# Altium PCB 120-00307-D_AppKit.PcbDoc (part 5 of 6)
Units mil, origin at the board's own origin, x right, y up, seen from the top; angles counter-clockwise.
Board outline 5150 x 3100 mil, 6 copper layers (L1, L2 (GND), L3-SIG, L4-SIG, L5 (PWR), L6), stack 61.956 mil thick; 413 components, 344 nets, 1685 pads, 1021 vias.
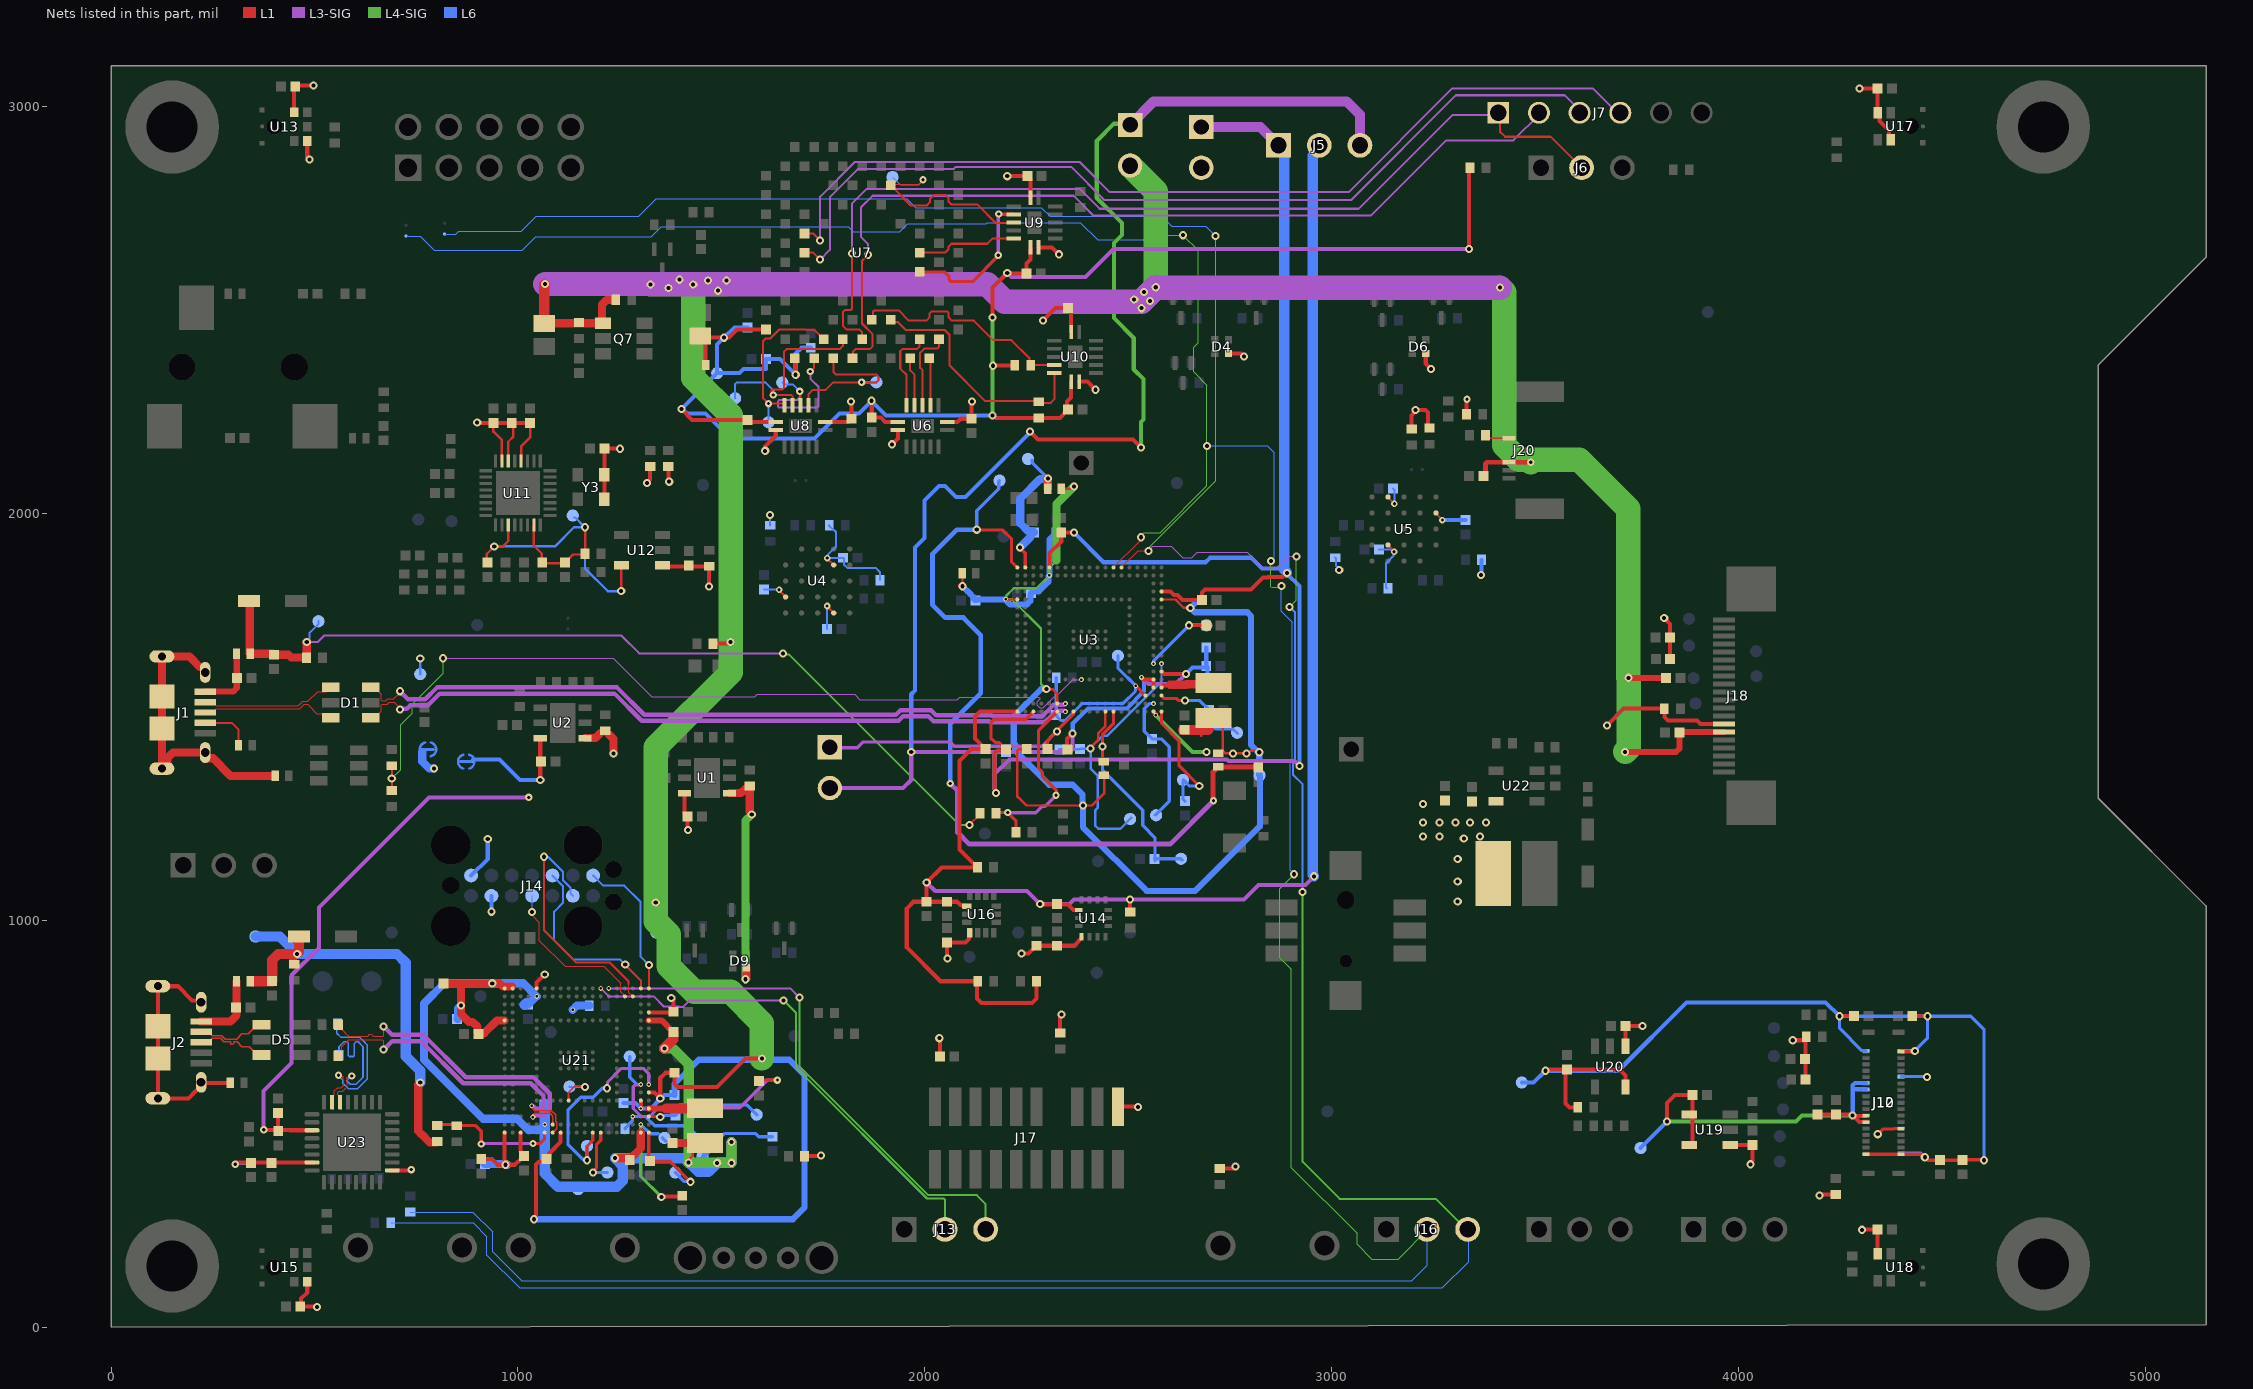
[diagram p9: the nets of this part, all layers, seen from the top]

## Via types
v1: diameter 20, hole 10, L1 to L6, tented both sides, 437 vias
v2: diameter 20, hole 10, L1 to L6, 330 vias
v3: diameter 12, hole 6, L1 to L6, tented both sides, 120 vias
v4: diameter 18, hole 8, L1 to L6, 93 vias
v5: diameter 16, hole 8, L1 to L6, tented both sides, 41 vias

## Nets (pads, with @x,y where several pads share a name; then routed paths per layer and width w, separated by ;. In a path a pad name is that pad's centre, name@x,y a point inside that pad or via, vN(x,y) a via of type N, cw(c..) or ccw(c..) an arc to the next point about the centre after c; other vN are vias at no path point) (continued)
SEUART_RX: J16.3 R105.1 S8.2 U3.A14 | length 8155.6
  L1 w3: U3.A14@2483.74,1867.16 2524.57,1908 v2(2550,1908)
  L3-SIG w3: v2(2550,1908) 2561,1919 2606,1919 2634,1891 2656,1891 2670,1905 2793,1905 2832,1866 2865,1866 2894,1895 v2@2914,1895 ; v2@2913.5,1894.5 v2(2914,1894)
  L4-SIG w3: v2(2550,1908) 2553.25,1911.25 2553.25,1918.25 2715,2080 v2(2715,2682) ; v2(2897,1770) 2914,1787 v2(2914,1894)
  L4-SIG w5: v2(2929,1069) 2929,406 3020,315 3256,315 J16.3@3337,234
  L6 w3: R105.1@687.68,256 890,256 924,222 924,176 1004,96 3272,96 3337,161 3337,243 J16.3@3339,245 ; S8.2@820,2686.7 847.7,2686.7 855,2694 1008,2694 1045,2731 1297,2731 1340,2774 1956,2774 1978,2752 2287,2752 2309,2730 2584,2730 2608,2706 2691,2706 v2(2715,2682)
  L6 w5: v2(2897,1770) 2910.5,1756.5 2910.5,1390.42 2905.5,1385.42 2905.5,1357.5 2929,1334 v2(2929,1069)
SEUART_RX_J: J13.3 U21.A14 | length 1307.3
  L3-SIG w5: v3(1223.43,832.48) 1669.52,832.48 v2(1692,810)
  L4-SIG w5: v2(1692,810) 1692,641 2009,324 2128,324 2150,302 J13.3@2150,240
SEUART_TX: J16.2 R106.1 S9.2 U3.A13 | length 8159.7
  L1 w3: U3.A13@2464.05,1867.16 2528.75,1931.86 2528.75,1938.25 v2(2532,1941.5)
  L4-SIG w3: v2(2532,1941.5) 2532,1946.1 2536.76,1950.86 2536.76,1951.24 2538.52,1953 2579.51,1953 2694,2067.49 v2(2694,2166) 2694,2315 2661,2348 2661,2408 2672,2419 2672,2647 v2(2635,2684) ; v2(2851,1883) 2851,1819.76 2852.76,1818 2866.74,1818 2867.13,1818.39 2873.75,1818.39 v2(2877,1821.64) ; v2(2908,1113) 2873,1078 2873,908 2901,880 2901,392 3063,230 3063,203 3099,167 3164,167 J16.2@3242,245
  L6 w3: S9.2@725,2681.7 759.7,2681.7 ; R106.1@735,282.63 889.37,282.63 938,234 938,185 1009,114 3197,114 3235,152 J16.2@3235,240 J16.2@3235,255 ; 760,2682 759.7,2681.7 ; v2(2635,2684) 2581,2684 2570,2673 2425,2673 2383,2715 2154,2715 2151,2712 1958,2712 1939,2693 1824,2693 1812,2705 1353,2705 1328,2680 1044,2680 1011,2647 795,2647 760.3,2681.7 759.7,2681.7 ; v2(2694,2166) 2842,2166 2859,2149 2859,1891 v2(2851,1883) ; v2(2877,1821.64) 2877,1759 2903.5,1732.5 2903.5,1393.32 2898.5,1388.32 2898.5,1122.5 v2(2908,1113)
SEUART_TX_J: J13.2 U21.A13 | length 1226.4
  L3-SIG w5: v3(1203.74,832.48) 1223.43,812.8 1334.2,812.8 1359,788 1395,788 1396,787 1407,787 1423,803 v2(1653,803)
  L4-SIG w5: v2(1653,803) 1684,772 1684,637.69 2005.69,316 2047.07,316 2050,313.07 J13.2@2050,240
T_INT_3V3: J20.6 R91.2 | length 58.7
  L1 w4.72: R91.2@3378,2186 3379.17,2184.83 J20.6@3436.21,2184.83
TCK_J: J14.9 U21.B17 | length 614.2
  L1 w3: 1272,843 1272,836.6 1272.22,836.38 1272.22,821.21 1280.63,812.8 U21.B17@1282.48,812.8
  L1 w5: v2(1064,1156) 1064,976 1144,896 1226,896 1272,850 1272,843
  L6 w5: v2(1064,1156) 1074.15,1156 1111,1119.15 1111,1098 1129.68,1079.32 1129.68,1065.32 J14.9@1135,1060
TDI_J: J14.5 U21.A18 | length 453.1
  L1 w5: v2(1264,891) 1264,890 1302.16,851.84 U21.A18@1302.16,832.48
  L6 w5: J14.5@1085,1110 1111,1084 1111,1043 1089,1021 1089,951 1137,903 1252,903 v2(1264,891)
TDO_J: J14.11 U21.B16 | length 397.4
  L1 w3: v2(1035,1020) 1035,1012 1053,994 1053,950 1116,887 1211,887 1253,845 1253,824 1263,814 1262.8,813.8 U21.B16@1262.8,812.8
  L6 w3: v2(1035,1020) J14.11@1035,1060
TMS_J: J14.7 U21.A19 | length 364.8
  L1 w5: U21.A19@1321.85,832.48 1321.85,889.85 v2(1322,890)
  L6 w5: J14.7@1185,1110 1210,1085 1262,1085 1301,1046 1301,911 v2(1322,890)
USB_CYP_N: R97.1 U23.15 | length 402.4
  L1 w3: U23.15@543.22,552.66 543.22,565.12 U23.15@547.26,569.16 ; U23.15@547.3,569.16 549.06,570.91 549.06,580.31 556.75,588 566,588 572,594 572,605.91 571.16,606.75 571.16,614.55 569.4,616.31 561.69,616.31 v4(559,619)
  L1 w3.2: U23.15@543.22,546.73 U23.15@543.22,552.66 ; v4(559,619) v4@564,619
  L6 w3.8: R97.1@555,750 555,722 565.2,711.8 611.47,711.8 619.64,703.64 629.8,693.47 629.8,609.53 606.47,586.2 582.93,586.2 569.6,599.53 569.6,607.4 559,618 v4(559,619)
USB_CYP_P: R98.1 U23.14 | length 389.3
  L1 w3: U23.14@558.82,569.16 557.06,570.91 557.06,577 560.06,580 569.31,580 580,590.69 580,609.22 579.16,610.07 579.16,612.55 580.91,614.31 588.62,614.31 v4(591.32,617) ; U23.14@558.86,569.16 562.9,565.12 U23.14@562.9,552.66
  L6 w3.8: R98.1@560.32,667 560.32,689 572.32,701 580.32,701 583.32,698 583.32,667.23 585.54,665 596,665 598.32,667.32 598.32,697 602.32,701 607.32,701 619.32,689 619.32,614 602.32,597 587.72,597 580.72,604 580.72,607.4 590.32,617 v4(591.32,617)
USB_D_ID: FB2.1 J1.4 | length 126.3
  L1 w5: J1.4@231.3,1485.04 296.96,1485.04 313,1469 FB2.1@313,1431
USB_D_N: D1.1 J1.2 | length 331.4
  L1 w3: J1.2@231.3,1536.22 250,1536.22 256.37,1529.85 256.37,1529.18 258.13,1527.43 459.94,1527.43 470.93,1538.41 483.91,1538.41 507.58,1562.09 529.69,1562.09 D1.1@540,1572.4
USB_D_P: D1.3 J1.3 | length 331.3
  L1 w3: J1.3@231.3,1510.63 250,1510.63 256.37,1517 256.37,1517.67 258.13,1519.43 463.26,1519.43 474.24,1530.41 483.74,1530.41 485.5,1528.66 485.5,1527.99 505.58,1507.91 529.69,1507.91 D1.3@540,1497.6
USB_D_SH: FB3.1 J1.S1 J1.S2 J1.S3 J1.S4 J1.S5 J1.S6 | length 711.3
  L1 w20: J1.S6@125,1372.83 J1.S5@125,1471.26 J1.S4@125,1550 J1.S3@125,1648.43 192.57,1648.43 218.08,1622.92 228.72,1622.92 231,1620.64 J1.S1@231,1610 ; J1.S6@137.86,1377 138.55,1377.69 138.55,1398.55 152.2,1412.2 J1.S2@231.3,1412.2 ; J1.S2@233.88,1398.34 250.66,1398.34 294,1355 FB3.1@403.27,1355
USB_D_V: C3.1 FB1.1 J1.1 | length 163.5
  L1 w15: J1.1@231.3,1561.81 299.81,1561.81 309,1571 FB1.1@309,1653
USB_D_VBUS: C1.1 D7.2 FB1.2 R2.2 R100.1 TP3.1 | length 2243.6
  L1 w5: FB1.2@341,1655.73 FB1.2@341.73,1655 ; R2.2@481,1649 R2.2@483,1647 ; v2@2111,1232 2111,1235.72 2136.32,1261.03 R100.1@2136.32,1263
  L1 w20: FB1.2@341,1655.73 D7.2@341,1787 ; FB1.2@341.73,1655 C1.1@398,1655 ; C1.1@400,1652.72 436.28,1652.72 443,1646 R2.2@480.31,1646 ; R2.2@481,1649 v2(481,1684)
  L3-SIG w5: v2@480,1684 v2(481,1684) 508,1684 524,1700 1254,1700 1298,1656 v2(1652,1656)
  L4-SIG w5: v2(1652,1656) 1654.87,1653.13 1666.95,1653.13 2086.08,1234 v2(2110,1234)
  L6 w5: v2(481,1684) 488,1691 488,1707 510,1729 TP3.1@510,1735
USB_DEV_N: D1.6 U3.V7 | length 1813.5
  L1 w3: D1.6@638.43,1572.4 648.27,1572.4 664.58,1556.09 664.58,1540.76 666.34,1539 675.69,1539 680.69,1544 694.5,1544 710,1559.5 v2(710,1563)
  L3-SIG w11: v2(710,1563) 729.9,1543.1 772.29,1543.1 801.39,1572.2 1243.7,1572.2 1310.69,1505.21 1929.49,1505.21 1940.59,1516.3 2015.6,1516.3 2027.9,1504 2165.23,1504 2167.23,1502 2289.55,1502 2317.73,1530.18 2343.6,1530.18 v3(2345.95,1532.52)
USB_DEV_P: D1.4 U3.W7 | length 1809.1
  L1 w3: D1.4@638.43,1497.6 648.27,1497.6 664.58,1513.91 664.58,1529.24 666.34,1531 679,1531 684,1536 695.5,1536 710,1521.5 v2(710,1518)
  L3-SIG w11: v2(710,1518) 711.72,1519.72 727.22,1519.72 735.6,1528.1 778.5,1528.1 807.6,1557.2 1237.49,1557.2 1304.48,1490.21 1935.71,1490.21 1946.8,1501.3 2009.39,1501.3 2021.69,1489 2159.01,1489 2161.01,1487 2295.77,1487 2323.95,1515.18 2342.9,1515.18 2345.24,1512.84 v3(2345.95,1512.84)
USB_FTDI_N: R95.1 U21.V7 | length 796.9
  L1 w3: R95.1@558.68,743 558.68,741.03 576.01,723.71 576.01,722.49 584,714.5 631,714.5 ; 631,715 633,717 ; 633,718 635,720 640,720 642,718 ; 642,717.5 645,714.5 668.24,714.5 670,716.26 v2(670,739)
  L1 w3.2: v3@1037,514 v3(1037,516) 1037,520 1042,525 1079,525 1085.63,518.37 U21.V7@1085.63,497.84
  L3-SIG w4.2: v3(1037,516) v3@1037,517.16
  L3-SIG w11: v2(670,739) 691,718 768,718 872,614 1038.21,614 1078,574.21 1078,536.23 1062.77,521 1042.27,521 1037.27,516 v3(1037,516)
USB_FTDI_P: R96.1 U21.W7 | length 797.4
  L1 w3: R96.1@557.68,667 567.01,676.33 567.01,689.51 584,706.5 668.24,706.5 670,704.74 v2(670,682)
  L1 w3.2: R96.1@561,667 R96.1@561.6,667.6 ; v3(1034,544) 1034,540 1042,532 1081.9,532 1092.63,521.27 1092.63,513.05 1093,512.68 1093,505.68 1095.15,503.53 1095.15,487.67 U21.W7@1085.63,478.15
  L3-SIG w11: v2(670,682) 691,703 761.79,703 865.79,599 1032,599 1063,568 1063,542.44 1056.56,536 1045,536 1039.28,541.72 1036.55,541.72 1034.27,544 v3(1034,544)
USB_ID: R8.2 R12.1 U3.R9 | length 2090.9
  L1 w5: R12.1@690,1317 v2(690,1348.5) R8.2@690,1380
  L3-SIG w3: v2(816,1644) 1234,1644 1328.9,1549.1 1582.59,1549.1 1588.99,1555.5 1828,1555.5 1841,1542.5 2080.01,1542.5 2086.01,1548.5 2282.02,1548.5 2283.78,1546.74 2283.78,1544.26 2276.39,1536.87 2276.39,1528.17 2282.54,1522.02 2291.24,1522.02 2318.32,1549.1 2322.1,1549.1 2364.57,1591.57 v3(2385.32,1591.57)
  L4-SIG w3: v2(690,1348.5) 712,1370.5 712,1481 740,1509 740,1531 816,1607 v2(816,1644)
USB_ID_J: TP54.1 U21.R9 | length 106.4
  L1 w5: U21.R9@1125,556.89 1125,577 1141,593 1154.57,593 1154.7,592.87 1162.13,592.87 v2(1165,590)
  L6 w5: TP54.1@1127,591 1128,590 v2(1165,590)
USB_U_N: D5.1 J2.2 | length 157.1
  L1 w3.2: J2.2@221.3,725.59 240,725.59 246.27,719.32 246.27,718.17 248.15,716.3 271.9,716.3 280.19,708 308.94,708 321.69,720.75 337.29,720.75 354.54,738 D5.1@358,738
USB_U_P: D5.3 J2.3 | length 158.6
  L1 w3.2: J2.3@221.3,700 240,700 246.27,706.27 246.27,707.42 248.15,709.3 269,709.3 277.3,701 293,701 294,700 294,696.87 295.87,695 299.13,695 301,696.87 301,700 302,701 309.94,701 321.69,689.25 339.29,689.25 351,677.54 D5.3@351,675
USB_U_SH: FB5.1 J2.S1 J2.S2 J2.S3 J2.S4 J2.S5 J2.S6 | length 598.4
  L1 w10: J2.S1@221.3,798.43 217.09,802.64 199.36,802.64 164.2,837.8 J2.S3@115,837.8 J2.S4@115,739.37 J2.S5@115,660.63 J2.S6@115,562.2 190.2,562.2 209.39,581.39 209.69,581.39 221.3,593 J2.S2@221.3,601.57 222.87,600 FB5.1@293.27,600
USB_U_V: C8.1 FB4.1 J2.1 | length 176.9
  L1 w20: J2.1@221.3,751.18 293.18,751.18 308.27,766.27 FB4.1@308.27,850
USB_U_VBUS: C7.1 D8.2 FB4.2 R16.2 R103.1 TP4.1 | length 1095
  L1 w20: 447,916 447.2,915.8 447.2,892.51 448.03,891.69 R16.2@450,891.69 ; v2(760,601) 755.2,596.2 755.2,481.47 763.39,473.28 764.06,473.28 783.35,454 R103.1@800,454
  L1 w25: FB4.2@348,850 C7.1@396,850 ; C7.1@396,850.72 396,902.36 410.64,917 447,917 ; v2@462,922 D8.2@462,960
  L6 w25: TP4.1@355,960 414.5,960 v2(457.5,917) ; v2@467,917 703,917 724.18,895.82 724.18,665.75 760,629.94 v2(760,601)
USB_VB_J: R103.2 R104.1 U21.W6 | length 326.2
  L1 w8: R103.2@798,497.69 850,497.69 R104.1@851,497.69 ; R104.1@850,495.69 895.31,495.69 910,481 v4(910,450) ; v4(1037,451) 1054,451 1065.59,462.59 1065.59,477.8 U21.W6@1065.95,478.15
  L3-SIG w8: v4@910,451 v4(1037,451)
USB_VB_T: R100.2 R101.1 U3.W6 | length 472.6
  L1 w8: R100.2@2175.69,1263 2177.68,1265 v4(2204,1265) v4@2206,1267 ; v4@2207,1268 2207,1262 2224.32,1244.68 R101.1@2224.32,1216 ; v4(2323,1307) 2324,1308 2324,1319.03 2290,1353.03 2290,1356 2289,1357 2289,1363.97 2280,1372.97 2280,1466.57 U3.W6@2326.26,1512.84
  L3-SIG w8: v4(2204,1265) 2204,1264 2272.96,1264 2288.96,1280 2296,1280 v4(2323,1307)
V_1V2: C89.2 C90.2 C94.2 J10.23 J10.24 J12.23 J12.24 TP36.1 U19.4 U19.5 | length 1099
  L1 w10: v1(3825,505) 3825,551 3844,570 C94.2@3887.28,570 3887.28,452.6 3882.28,447.6 U19.5@3879.75,447.6 ; C89.2@4195,522.28 C90.2@4240,522.28 4276.01,522.28 4278.29,520 v1(4281,520) v1@4281.75,519.25 ; J10.23@4314.17,503.5 4297.5,503.5 v1@4281.75,519.25 ; J10.24@4314.17,519.25 v1@4281.75,519.25
  L4-SIG w10: v1(3825,505) 4142,505 4157,520 v1(4281,520)
  L6 w10: TP36.1@3760,440 v1(3825,505) ; v1@4281.51,520.51 4281.51,584.49 ; J12.24@4314.17,584.49 4281.51,584.49 ; J12.23@4314.17,600.24 4286.86,600.24 4281,594.38 4281,585 4281.51,584.49
V_1V8_C: C67.2 C68.2 C74.2 R61.1 TP29.1 U11.19 U11.23 U12.5 | length 944.8
  L1 w6: C68.2@924,1879 924,1901 v1(942,1919) 963,1919 976.38,1932.38 U11.19@976.38,1971.26 ; U11.23@1039.37,1971.26 1039.37,1920.63 1059,1901 C67.2@1059,1883 ; C67.2@1060,1879.03 1061.03,1878 C74.2@1115,1878 ; C74.2@1116,1879.72 1135.28,1899 R61.1@1160,1899 ; v1(1165,1966) 1165.32,1965.68 R61.1@1165.32,1901 ; U12.5@1253,1870 1254,1869 v1(1254,1809)
  L6 w6: v1(942,1919) 1091,1919 1138,1966 v1@1163,1966 ; TP29.1@1139,1990 1141,1990 v1@1164,1967 ; v1(1165,1966) 1165,1865 1221,1809 v1(1254,1809)
V_1V8_R: C37.2 C38.2 C39.2 C40.2 C41.2 C42.2 C43.2 C45.2 C47.2 C55.2 C57.2 C64.2 C65.2 C66.2 C75.1 C76.2 C78.2 C79.1 C80.1 C83.1 C84.1 C91.2 C92.2 C106.2 C107.2 C108.2 C111.2 C116.1 C117.1 C118.1 C132.2 C133.2 C134.2 J4.2 J10.13 J12.13 J14.1 J14.13 J17.1 J18.7 R26.1 R27.2 R28.2 R29.2 R30.2 R31.1 R39.2 R48.1 R49.1 R52.1 R53.1 R69.1 R71.2 R78.2 R85.2 R86.1 R90.1 R94.2 S2.2 TP2.1 U4.B4 U4.D1 U4.E4 U5.B4 U5.D1 U5.E4 U6.1 U6.8 U8.1 U8.8 U9.1 U9.8 U10.1 U10.8 U11.4 U11.6 U11.7 U13.2 U13.7 U14.8 U15.7 U16.8 U17.2 U17.7 U18.7 U21.A5 U21.D19 U21.W1 U21.W3 U23.1 U23.23 Y3.1 Y3.4 | length 5188.6
  L1 w5: v5(1642,1812.47) 1642,1810.89 U4.D1@1658.29,1794.6 ; v5(1760,1772.47) 1760,1771.63 U4.E4@1776.4,1755.23 ; v5(1760.77,1890.23) 1760.77,1888.97 U4.B4@1776.4,1873.34 ; U5.E4@3138.69,2040.06 v5@3154.77,2023.99 ; U5.B4@3139,1922.26 3139,1921.63 3154,1906.63 v5(3154,1906) ; U5.D1@3256.62,2000.51 v5@3272.77,1984.36
  L1 w6: C65.2@940,2222.28 940,2201 960.63,2180.37 U11.7@960.63,2128.74 ; U11.6@976.38,2128.74 976.38,2176.38 989,2189 989,2218.28 C64.2@985,2222.28 ; U11.4@1007.87,2128.74 1007.87,2164.87 1030,2187 C66.2@1030,2222.28
  L1 w8: v1(4343,474) 4356,487 4382.04,487 4382.8,487.76 J10.13@4400,487.76
  L1 w10: v4(305,400) 309.94,404.94 U23.23@499.86,404.94 ; U13.2@450,2985.87 450,3047.28 C75.1@452.72,3050 454.72,3052 v1(498,3052) ; U15.7@482.28,110 482.28,85 467.28,70 467.28,52.28 C79.1@465,50 505,50 v1(506,49) ; U13.7@482.28,2915 482.28,2875.72 v1(488,2870) ; U23.1@685,385.26 736.26,385.26 v4(738,387) ; v1(900,2224) 901.72,2222.28 C65.2@940,2222.28 C64.2@985,2222.28 C66.2@1030,2222.28 ; C111.2@910,412.72 936.28,412.72 950,399 v1(970,399) ; U21.W1@967.52,478.15 967.52,408.55 968.09,407.98 968.09,400.91 v1(970,399) ; U21.W3@1006.89,478.15 1006.89,433.5 1007.8,432.59 1007.8,427.64 C108.2@1015,420.43 999.77,405.2 999.48,405.2 993.28,399 v1(970,399) ; U21.A5@1046.26,832.48 1046.26,847.26 v1(1066,867) ; Y3.4@1212.48,2034.49 Y3.1@1212.48,2095.51 1212.48,2159.76 C57.2@1212.72,2160 1250,2160 v1(1251,2159) ; v1(1317,2075) 1325,2083 R52.1@1325,2115.32 ; U21.D19@1321.85,773.42 1380.71,773.42 C107.2@1382.28,775 1382.28,803.72 v1(1377,809) ; R53.1@1370,2115.32 1370,2080 v1(1372,2078) ; v1(1608,2154) 1608,2165 1633.98,2190.98 U8.1@1633.98,2205.16 ; R78.2@1704.69,420 1743,420 v1(1745,422) ; U8.8@1756.02,2224.84 1812.13,2224.84 C45.2@1820,2232.72 1820,2274 v1(1819,2275) ; v1(1920,2170) 1933.98,2183.98 U6.1@1933.98,2205.16 ; v1(2036,710) 2037.28,708.72 C116.1@2037.28,665 ; v1(2056,906) 2055,907 C80.1@2055,945 2100,945 2108.58,953.58 2108.58,967.24 U16.8@2110.47,969.13 ; U6.8@2056.02,2224.84 2080.84,2224.84 2088.72,2232.72 C43.2@2115,2232.72 2115,2274 v1(2116,2275) ; v1(2203,2829) 2204,2830 C47.2@2252.28,2830 2260.16,2822.13 U9.8@2260.16,2776.02 ; v1(2238,918) 2255.72,918 C76.2@2275,937.28 C78.2@2325,937.28 2367.95,937.28 2378.58,947.91 2378.58,948.95 2384.52,954.88 2385.39,954.88 2385.47,954.96 U14.8@2385.47,959.23 ; U9.1@2279.84,2653.98 2313.02,2653.98 v1(2330,2637) ; v1(2291,2474) 2322,2505 C55.2@2352.28,2505 2360.16,2497.13 U10.8@2360.16,2446.02 ; R85.2@2333,722.69 2333,765 v1(2336,768) ; U10.1@2379.84,2323.98 2400.02,2323.98 v1(2420,2304) ; J17.1@2475,541.77 2523.23,541.77 v1(2524,541) ; R39.2@2725,389.69 2758.69,389.69 v1(2764,395) ; R48.1@3197,2201.25 3197,2205.72 3197,2241.29 3207,2251.29 v1(3207,2254) 3231.14,2254 3237,2248.14 R49.1@3237,2204.8 ; R90.1@3332.31,2244 3332.31,2280.32 v4(3333,2281) ; v1(3677,1479) 3718,1520 R86.1@3818.31,1520 3818.31,1499.68 3827,1491 3899,1491 3907.48,1482.52 J18.7@3965,1482.52 ; v1(3818,1743) 3832.72,1728.28 C118.1@3832.72,1642 ; v1(4134,705) 4158.31,705 4159.52,706.2 4161.49,706.2 R71.2@4165.72,710.43 ; C91.2@4165.72,608 R71.2@4165.72,710.43 ; R71.2@4167.31,714 4167.31,712.03 R71.2@4165.72,710.43 ; v1(4200,323) 4202.63,325.63 R69.1@4240,325.63 ; v1(4298,3045) C83.1@4342.28,3045 4342.64,3044.65 4342.64,2985.98 4347.21,2981.41 4347.21,2964.79 4370.62,2941.38 4370.62,2924.38 U17.2@4375,2920 ; v1(4304,239) 4305,240 C84.1@4342.28,240 4342.28,180.35 U18.7@4342.64,180
  L6 w5: C40.2@1605,1813.28 1641.18,1813.28 v5(1642,1812.47) ; R26.1@1620,1971 v2(1620,1996) ; C39.2@1760,1716 v5(1760,1772.47) ; R28.2@1765.31,1971 1765.31,1969.03 1773.64,1960.7 1775.61,1960.7 1782,1954.32 1782,1918.32 1762.87,1899.19 1762.87,1892.34 v5(1760.77,1890.23) 1798.8,1890.23 C37.2@1799.57,1891 1801.78,1888.79 1801.78,1874.22 1810,1866 1880,1866 1890,1856 R27.2@1890,1836 ; R29.2@3009,1891.31 3011.08,1889.23 3011.08,1871.43 3019,1863.51 v1(3019,1861) ; C38.2@3116.72,1911 3146.02,1911 3152.02,1905 v5@3153,1905 ; R30.2@3137,1815 3134,1818 3134,1877 3152.54,1895.54 3152.54,1904.54 v5@3153,1905 ; C41.2@3151.72,2061 3155,2057.72 v5@3155,2025 ; v5@3153.5,1905.5 v5(3154,1906) ; v5@3154,1905 v5@3153,1905
  L6 w6: TP2.1@760,1605 v1(760,1643)
  L6 w8: J12.13@4400,615.98 4463.02,615.98 v1(4464,615)
  L6 w10: v4@306,400 307.16,400 310.88,403.72 C132.2@344,403.72 ; J14.1@885,1110 926,1151 v1(926,1200) ; v1(935,1021) J14.13@935,1060 ; v5@3274,1984 3274.28,1983.72 C42.2@3329,1983.72 ; v1(3368,1849) 3368.69,1849.68 R31.1@3368.69,1886
  L6 w20: 765,1414 765,1406.66 765,1390.05 782.05,1373 v1(794,1373) ; C106.2@918.72,401 972,401 v1@974,399 ; v3(1134.99,779.99) 1145,790 R94.2@1175.31,790
  other v5: 3272.77,1983.77 3154.77,2023.77
V_2V6V8: C85.2 C86.2 C87.2 C88.2 C96.2 J10.1 J10.17 J10.18 J12.1 J12.17 J12.18 R70.1 TP39.1 U20.5 | length 2616.7
  L1 w8: v1(4249,764) 4250,765 C87.2@4285,765 ; J10.18@4314.17,424.76 J10.17@4400,424.76 4451.24,424.76 ; J10.1@4400,676.73 4431.73,676.73 v2(4433.98,678.98) ; C88.2@4427.72,765 4428.72,764 v1(4465,764) ; 4466,410 4550,410 C85.2@4551,411 4603,411 v1(4604,410)
  L1 w10: v1(3526,630) 3529.28,633.28 C96.2@3579,633.28 ; R70.1@3605.63,540 3585,540 3575,550 3575,629.28 C96.2@3579,633.28 ; U20.5@3722.4,589.75 3722.4,618.6 3707.72,633.28 C96.2@3579,633.28
  L6 w8: J12.18@4314.17,678.98 4313.65,679.5 4303.5,679.5 4249,734 v1(4249,764) v1(4465,764) ; J12.1@4400,427.01 4448.99,427.01 v1(4458.62,417.38) ; J12.17@4400,678.98 v2(4433.98,678.98) 4465,710 v1(4465,764) ; v1(4604,410) 4604,732 4572,764 v1(4465,764)
  L6 w10: TP39.1@3468,601 3497,601 v1(3526,630) 3705,630 3873,798 4215,798 v1(4249,764)
V_3V3: C54.2 C98.2 C99.2 C100.2 C112.2 C119.2 C120.1 C124.1 J3.2 J18.6 J20.3 Q7.4 R5.1 R42.1 R43.2 S1.2 TP1.1 U21.P19 U21.R18 U21.T18 U21.W8 | length 9684.2
  L1 w10: v1(1040,265) 1040,267.71 1045,272.71 1045,400 1051.05,406.05 1063.33,406.05 C99.2@1070,412.72 1077.2,419.92 1077.2,427.2 1105.32,455.32 U21.W8@1105.32,478.15 ; C54.2@1065,2467.15 C54.2@1065.25,2467.4 ; v1@1065,2562 v1(1067,2564) ; Q7.4@1207,2469.54 Q7.4@1209.13,2467.4 ; v3(1302.16,537.2) U21.R18@1302.16,556.89 ; U21.P19@1321.85,576.58 1335.43,576.58 v1(1350,562) 1350,611.65 1363.35,625 C100.2@1385,625 1385,597.44 1392.44,590 1490,590 1560,660 v2(1600,660) ; R5.1@1479.68,1680 1516.29,1680 1520.29,1684 v1(1523,1684) ; C120.1@3855.72,1461 C120.1@3857.55,1462.83
  L1 w12: C124.1@3375,2094 3378.46,2097.46 3378.46,2122.2 3382.03,2125.77 J20.3@3436.21,2125.77 3436.31,2125.87 3490.87,2125.87 v4@3491,2126
  L1 w15: v1(3722,1414) 3846.93,1414 3855.72,1422.79 C120.1@3855.72,1461 ; v1(3730,1596) 3731.35,1596 3732.35,1595 C119.2@3822.28,1595 ; C120.1@3857.55,1462.83 J18.6@3965,1462.83
  L1 w20: C54.2@1065.25,2467.4 Q7.4@1209.13,2467.4 ; Q7.4@1207,2469.54 1207,2514 1218,2525 R43.2@1240.63,2525
  L1 w25: C54.2@1065,2467.15 v1@1065,2562
  L3-SIG w25: v1@1430,2564 v1(1431,2563)
  L3-SIG w60: v1(1067,2564) 1325,2564 v1(1326,2563) 1429,2563 v1@1430,2564 ; v1(1431,2563) 2154,2563 2197,2520 2532,2520 v1(2568,2556) ; v1@2568,2555 v1(3414,2555)
  L4-SIG w25: v1(3730,1596) v1@3731,1595
  L4-SIG w60: v1(1326,2563) v1(1431,2563) ; 1509,2563 v1(1431,2563) ; v2(1600,660) 1600,747 1523,824 1433.72,824 1371,886.72 1371,966 1339,998 v1(1339,1044) 1339,1425 1523,1609 v1(1523,1684) 1523,2241 1431,2333 v1(1431,2563) ; J3.2@2505,2855 2568,2792 v1(2568,2556) 2532,2520 ; v1(3414,2555) 3425,2544 3425,2167.29 3460.29,2132 3484,2132 v4(3490,2126) 3496.14,2132.14 3609,2132.14 3730,2011.14 v1(3730,1596) ; v1(3722,1414) 3731,1423 v1@3731,1595
  L6 w10: C98.2@1260,550.28 1289.09,550.28 v3(1302.16,537.2) 1327.2,537.2 1350,560 v1(1350,562) 1352.48,562 1360.48,570 C112.2@1385,570 ; v1(1339,1044) v1@1340,1043
  L6 w15: v1(1040,265) 1676,265 1705,294 1705,619 1667,657 1444.56,657 1385,597.44 C112.2@1385,570 ; TP1.1@1340,970 v1@1340,1043
  L6 w25: v1(1339,1044) 1339,1072
  other v1: 2533.11,2504.56 2554.11,2522.56 2515.11,2525.56 2539.11,2544.56 1492.11,2547.56 1370.11,2554.56 1467.11,2572.56 1513.11,2572.56 1397.11,2574.56
V_3V3_W: C44.1 C46.1 C48.1 C49.2 C50.2 C51.2 C52.2 C56.1 FB10.2 R40.1 R46.2 R47.2 TP25.1 U6.14 U7.AA3 U7.W1 U8.14 U9.14 U10.14 | length 4285.7
  L1 w10: v1(1402,2256.5) 1428.5,2230 C46.1@1565,2230 1570.16,2224.84 U8.14@1633.98,2224.84 ; C52.2@1448,2436.43 C52.2@1452.43,2432 ; FB10.2@1461.73,2365 1461.73,2422.69 C52.2@1452.43,2432 ; U7.W1@1610,2452.05 1539.05,2452.05 1519,2432 v1(1507,2432) C52.2@1452.43,2432 ; U7.AA3@1680.87,2381.18 1683,2379.05 v1(1683,2341) ; v1(1869,2277) 1870,2276 C44.1@1870,2235.43 1892.28,2235.43 1902.87,2224.84 U6.14@1933.98,2224.84 ; v1(2167,2241) 2169.71,2241 2175.71,2235 R47.2@2280,2235 2332.28,2235 2350,2252.72 2350,2275 2360.16,2285.16 U10.14@2360.16,2323.98 ; v2(2167,2482) 2167,2555 v1(2203,2591) 2204,2590 C48.1@2250,2590 2250,2614 2260,2624 2260,2653.82 U9.14@2260.16,2653.98 ; v2(2167.68,2363) 2168.68,2364 R46.2@2221.31,2364 ; v1(3338,2650) 3338,2847.69 R40.1@3340.31,2850
  L3-SIG w10: v1(2203,2591) 2203.86,2591 2213.86,2581 2395,2581 2464,2650 v1@3337,2650
  L4-SIG w10: v1(2167,2241) v2(2167,2482) v2@2168,2483
  L6 w10: v1(1402,2256.5) 1413.5,2268 ; v1@1402,2257 1402,2252 1404.59,2254.59 1406.62,2254.59 1415.21,2246 1461,2246 1523,2184 1729,2184 1791,2246 1838,2246 v1(1869,2277) 1905,2241 v1(2167,2241) ; 1413.25,2268.25 TP25.1@1490,2345 ; C50.2@1565,2457.28 1532.28,2457.28 v1(1507,2432) 1490,2415 TP25.1@1490,2345 ; C51.2@1720,2407.28 1697.28,2407.28 1683,2393 v1(1683,2341) 1644,2380 C49.2@1610,2380 1610,2355 1555,2355 1545,2345 TP25.1@1490,2345
VDD_3V3: C10.2 C13.2 C14.2 C29.2 J3.1 J5.3 J21.2 U3.P19 U3.R18 U3.T18 | length 4310.9
  L1 w10: v2(2259,2201) 2278.5,2181.5 2512.5,2181.5 v2(2532,2162) ; C13.2@2351,1420 2350.09,1420.91 2350.09,1446.09 v1(2363,1459) ; v3@2533,1597 2538.43,1591.57 U3.R18@2562.48,1591.57 U3.T18@2562.48,1571.89 ; U3.P19@2582.16,1611.26 2588.43,1605 v1(2642,1605)
  L3-SIG w10: J21.2@1761,1322 1764,1325 J21.2@1767,1325 1947,1325 1967,1345 v2(1967,1414) 2356.81,1414 2363,1420.19 v1(2363,1459) ; v3(2533,1597.11) 2549.91,1580.2 2617.2,1580.2 v1(2642,1605)
  L3-SIG w25: J3.1@2505,2955 2563,3013 3037,3013 3070,2980 J5.3@3070,2905
  L4-SIG w10: v2(1967,1414) v2@1967,1416 ; J3.1@2505,2955 2502,2958 2465,2958 2423,2916 2423,2776 2485,2714 2485,2685 2465,2665 2465,2480 2514,2431 2514,2354.43 2538,2330.43 2538,2230.57 2532,2224.57 v2(2532,2162)
  L6 w10: v2(1967,1414) 1967,1555.54 1976,1564.54 1976,1916 2000,1940 2000,2031.46 2035.54,2067 2050.46,2067 2077.46,2040 2100,2040 2259,2199 v2(2259,2201) ; v1(2363,1459) 2364,1460 2364,1484 2401,1521 2497,1521 2539,1563 2539,1590.57 2533,1596.57 v3(2533,1597.11) ; J3.1@2501,2959 J3.1@2505,2955 ; v1(2642,1605) 2658,1621 2688.28,1621 C10.2@2692.28,1625 ; C29.2@2692.28,1670 C10.2@2692.28,1625 ; C14.2@2695,1575 2695,1622.28 C10.2@2692.28,1625
VDD_CORE_0V8: C11.2 C15.2 C16.2 C17.2 C18.2 C19.2 FB6.1 FB7.1 FB8.1 FB9.1 L3.2 TP11.1 U3.B5 U3.E1 U3.E19 U3.V6 U3.W18 | length 3983.2
  L1 w6: FB6.1@2092.27,1853 2093,1852.27 v2(2093,1821) ; v3@2200,1789 2200.57,1788.43 U3.E1@2227.84,1788.43 ; C15.2@2251,1420.72 2231.51,1420.72 2228,1417.2 2228,1304 2250,1282 v1(2389,1282) 2411,1282 2441,1312 FB9.1@2441,1354 ; v1(2299,1568) 2314,1568 2326.26,1555.74 U3.V6@2326.26,1532.52 ; FB7.1@2335.73,2060.81 2358.02,2060.81 2363.21,2066 v1(2367,2066) ; U3.E19@2582.16,1788.43 2616.57,1788.43 2637,1768 v1(2653,1768) ; 2680,1453 2680,1467.09 2680.11,1467.19 2680.11,1467.28 2680.11,1475.68 2701.51,1497.09 L3.2@2710,1497.09 2711.31,1497.09 2732.72,1475.68 2732.72,1417 2739.72,1410 v1@2794.51,1410 ; v1(2758,1410) v1@2794.51,1410 ; v1(2822.49,1413) 2818.7,1413 2814.7,1417 2801.51,1417 v1@2794.51,1410
  L1 w10: U3.W18@2562.48,1512.84 2568,1507.32 v3(2568,1504)
  L1 w20: v2@2092.27,1821.73 v2(2093,1821)
  L1 w25: C11.2@2635,1467.28 2680.11,1467.28 2696.28,1467.28 2698,1469
  L4-SIG w6: v1(2299,1568) 2286,1581 2286,1717 2214,1789 v3(2199,1789) 2200.11,1790.11 2200.11,1797.11 2219,1816 2262.03,1816 2262.23,1815.8 2272.18,1815.8 2272.38,1816 2274.98,1816 v3(2306.57,1847.59) 2306.57,1866.57 2324,1884
  L4-SIG w10: v3(2568,1504) 2658.76,1413.24 v1(2692.58,1413.24)
  L4-SIG w20: 2324,1884 2324,2023 v1(2367,2066)
  L6 w15: v2(2093,1821) 2105.3,1808.7 2105.84,1808.7 2111.99,1802.55 2111.99,1802.01 2120.01,1793.99 2120.01,1790.7 2123.94,1786.78 C17.2@2125.49,1786.78 ; C17.2@2127.27,1788 v3@2198,1788 ; v3@2199,1787 2210,1776 2250.96,1776 2259.74,1784.79 2259.74,1802.03 C19.2@2261.72,1804 2266.42,1808.7 2280.7,1808.7 2304,1832 2304,1846 v3@2306,1848 ; v1(2299,1568) 2286,1568 2219,1501 2219,1434.07 2222.7,1430.36 2222.7,1416.3 2306,1333 2364,1333 2388.04,1308.96 2388.04,1282.96 v1(2389,1282) 2389,1229 2546,1072 2665,1072 2824,1231 2824,1356 2822.49,1357.51 v1(2822.49,1413) 2821.13,1413 2818.63,1415.5 2817.5,1415.5 2802,1431 2802,1748.21 2793.21,1757 2664.29,1757 2653.29,1768 v1(2653,1768) 2667.3,1782.3 2681.3,1782.3 C18.2@2685,1786 ; v3@2306.57,1848 2306.57,1935.67 C16.2@2324,1953.09
  other v1: 2791,1410
VDD_CORE_0V8_J: C97.2 C101.2 C102.2 C103.2 C104.2 C105.2 C109.1 C110.1 L4.2 TP44.1 U21.A1 U21.A2 U21.B5 U21.E1 U21.E19 U21.V6 U21.W18 | length 2934.4
  L1 w6: C105.2@1270.43,415 C105.2@1275,410.43 ; C97.2@1380,452.28 C97.2@1380.2,452.09 ; v1(1419,404) 1419,411.09 1430.11,422.19 1430.11,430.68 1451.51,452.09 L4.2@1460,452.09
  L1 w15: U21.E19@1321.85,753.74 1353.54,753.74 C103.2@1382.28,725
  L1 w20: C109.1@816.72,844 934,844 v1@935,843 ; 858,842 860,840 v1(860,790) 860,770 880,750 888.86,750 900.58,738.28 900.58,722.14 C102.2@902.72,720 ; 917.2,722.2 948.74,753.74 U21.E1@967.52,753.74 ; v1(937,845) 955,845 963,837 U21.A2@986,837 ; v1(1239,415) C105.2@1270.43,415 ; C105.2@1275,410.43 1277.2,412.64 1277.2,414.61 1302.16,439.57 U21.W18@1302.16,478.15 ; C97.2@1380.2,452.09 L4.2@1451.51,452.09
  L1 w25: v1(1360,685) 1382.28,707.28 C103.2@1382.28,725
  L4-SIG w25: v1(1360,685) 1381,685 1420,646 v1@1420,404 ; v1@1419,403 v1@1420,404 ; v1(1419,404) v1@1420,404 ; v1(1525,455) 1525.01,404 v1@1420,404
  L6 w20: C110.1@852,757 852.92,757.92 852.92,782.92 v1(860,790) ; 1023,487 998,512 914,512 769,657 769,795 819,845 v1(937,845) 1014.17,845 v3(1046.26,812.91) 1045.19,812.91 C101.2@1025,792.72 ; 1025,485 1053.11,485 v3(1065.95,497.84)
  L6 w25: C101.2@1016.72,792.43 C101.2@1021,796.72 ; C104.2@1065,547.28 1065.95,546.34 v3(1065.95,497.84) 1065.95,377.4 1098.35,345 1243.36,345 1258,359.64 1258,395.49 1239,414.49 v1(1239,415) 1409,415 1443,381 1469,381 1492,404 1525.01,404 v1(1525,455)
  other v1: 1490.01,403.75 1525.01,403.75
VDD_DIG_1V8: C32.2 TP17.1 U3.U19 | length 243.2
  L1 w8: U3.U19@2582.16,1552.2 2589.37,1545 2620,1545 2624.94,1540.06 2639.94,1540.06 v1(2640,1540)
  L6 w8: v1(2640,1540) 2676.28,1540 C32.2@2699.28,1517 2699.28,1486.72 2716,1470 2758,1470 TP17.1@2769,1459
VDD_DIG_1V8_J: C113.2 TP48.1 U21.U19 | length 296.3
  L1 w8: U21.U19@1321.85,517.52 1348.48,517.52 v1(1350,516)
  L6 w8: v1(1350,516) 1353.25,516 1357.25,520 C113.2@1387.28,520 1390.57,523.29 1390.57,537.2 1399.37,546 1563,546 TP48.1@1587,522
VDD_IOFLEX: C28.2 C77.1 C81.1 C82.1 J5.2 R50.1 R51.1 R63.2 R66.2 U3.W1 U14.5 U16.5 | length 4386.4
  L1 w6: C82.1@2005,1045.43 C82.1@2005,1049.37
  L1 w10: C82.1@2005,1049.37 v1(2005,1093) 2042,1130 R66.2@2130,1130 2086,1174 2086,1392 2114.57,1420.57 C28.2@2149.86,1420.57 2124,1446.43 2124,1500.7 2136.14,1512.84 U3.W1@2227.84,1512.84 ; U16.5@2103.98,1034.68 2102.09,1036.57 2091.93,1036.57 2091.5,1037 2088,1037 2079.57,1045.43 C81.1@2055,1045.43 C82.1@2005,1045.43 1972.43,1045.43 1956,1029 1956,933 2039,850 R51.1@2130.32,850 2129,848.69 2129,808 2140,797 2264,797 2274.68,807.68 R50.1@2274.68,850 ; v1(2284,1040) 2285,1039 2352,1039 2366.32,1024.68 U14.5@2379.07,1024.68 ; R63.2@2505,1020 v1(2505,1051)
  L3-SIG w10: v1(2005,1093) 2026,1072 2252,1072 v1(2284,1040) 2356,1040 2366.77,1050.77 2504.77,1050.77 v1(2505,1051) 2785,1051 2821,1087 2936,1087 v1(2957,1108)
  L6 w25: v1(2957,1108) 2954,1111 2954,2879.25 2970,2895.25 J5.2@2970,2905
VDD_MIPI_0V8: C27.2 FB9.2 TP12.1 U3.W13 | length 537.5
  L1 w8: v1@2437,1425 2437,1392.73 FB9.2@2440,1389.73 ; v1(2437,1427) 2437,1456 2464.05,1483.05 U3.W13@2464.05,1512.84
  L6 w8: v1(2437,1427) 2437,1369.73 2536,1270.73 2536,1233 2566,1203 C27.2@2566,1151 ; C27.2@2564.72,1151 C27.2@2566,1151 ; C27.2@2566,1146 C27.2@2566,1151 ; TP12.1@2633,1148 TP12.1@2630,1151 C27.2@2566,1151
VDD_MIPI_0V8_J: TP45.1 U21.W13 | length 140.9
  L1 w8: v1(1185,380) 1185,382.69 1193,390.69 1193,448 1203.74,458.74 U21.W13@1203.74,478.15
  L6 w8: v1(1185,380) TP45.1@1220,380
VDD_MIPI_1V8: C30.2 C31.2 TP18.1 U3.N19 U3.W12 | length 773.8
  L1 w6: v1(2408,1422) 2408,1425.19 2427,1444.19 2427,1460.14 2444.37,1477.51 U3.W12@2444.37,1512.84
  L6 w6: C31.2@2331.32,1420 2381,1420 2383,1422 v1(2408,1422) ; TP18.1@2508,1252 TP18.1@2505,1249 2481,1225 2427,1225 2419,1233 2419,1270 2426,1277 2426,1355 2408,1373 v1(2408,1422) ; v3(2582.16,1630.95) 2582.16,1587.16 2448,1453 2437,1453 2408,1424 v1(2408,1422)
VDD_MIPI_1V8_J: TP49.1 U21.N19 U21.W12 | length 536.6
  L1 w8: v1(1170,410) 1170,445 1184.05,459.06 U21.W12@1184.05,478.15
  L3-SIG w8: v2(1219,587) 1220.06,588.06 1220.06,601.06 1254.63,635.63 1308.37,635.63 1321.85,622.15 v3(1321.85,596.26) v3@1321.85,596.15
  L6 w8: TP49.1@1170,445 v1(1170,410) 1167.7,412.3 1159.79,412.3 1123,449.09 1123,533 1155,565 1185,565 1207,587 v2(1219,587)
VDD_PLL_0V8: C26.1 FB8.2 TP13.1 U3.A1 | length 2116.2
  L1 w8: v1(2128,1960) 2128.92,1959.08 2180,1959.08 ; 2180,1959 2192,1959 2213.5,1937.5 2213.5,1881.5 U3.A1@2227.84,1867.16
  L1 w12: v4(2710,1293.5) 2710,1294 2709,1295 2709,1364.27 2715.2,1370.47 2715.2,1374.27 2718.2,1377.27 FB8.2@2722,1377.27 ; FB8.2@2727.51,1376.49 2819.22,1376.49 C26.1@2820,1375.72
  L3-SIG w12: v4(2063,1336) 2081,1318 2081,1216 2110,1187 2603.5,1187 v4(2710,1293.5)
  L6 w8: v1(2128,1960) 2128,2007 2181.81,2060.81 2181.81,2078.62 TP13.1@2184,2080.81
  L6 w12: v4(2063,1336) 2063,1483 2138,1558 2138,1701 2095,1744 2051,1744 2019,1776 2019,1900 2079,1960 v1(2128,1960)
VDD_SX_0V8: C25.1 FB7.2 TP14.1 U3.A2 | length 367.9
  L1 w8: v1(2234,1916) 2247.52,1902.48 U3.A2@2247.52,1867.16 ; FB7.2@2302.27,2060.81 FB7.2@2302.63,2061.18 ; v1@2302.63,2085.63 v1(2303,2086)
  L1 w20: FB7.2@2302.63,2061.18 v1@2302.63,2085.63
  L6 w8: TP14.1@2264.27,2131.36 2264.27,2124.73 v1(2303,2086)
  L6 w20: v1(2234,1916) C25.1@2260,1942 ; C25.1@2269,1953.09 2266.8,1955.3 2255.7,1955.3 2235,1976 2235,2036 2284,2085 v1@2301,2085
VDD_USB_3V3: C12.2 J21.1 U3.W8 | length 700
  L1 w3: U3.W8@2365.44,1512.65 U3.W8@2365.63,1512.84
  L1 w8: C12.2@2302,1420.72 2302,1441.33 v2@2323.67,1463 ; v2@2324,1464.25 2365.44,1505.7 U3.W8@2365.44,1512.65
  L3-SIG w8: J21.1@1767,1424 1834,1424 1848,1438 2063,1438 2073,1428 2288.67,1428 v2(2324.92,1464.25)
VDDIO_1V8: C20.2 C21.2 C22.2 C23.2 J4.1 J5.1 U3.A5 U3.D19 U3.W3 | length 4087.4
  L1 w8: C21.2@2194,1426 2193.72,1426 2182.72,1437 2173,1437 2163,1447 2163,1486 2171,1494 2248.37,1494 U3.W3@2267.2,1512.84
  L1 w10: v1(2175,1313) 2173.09,1314.91 2173.09,1321.98 2172,1323.07 2172,1411 2178.65,1417.65 2197.94,1417.65 C21.2@2200,1419.72 C21.2@2200.75,1420.46 ; U3.A5@2306.57,1867.16 2306.57,1902.21 2335.81,1931.44 C20.2@2335.81,1953.09 2366.91,1953.09 v1(2367,1953) ; U3.D19@2582.16,1808.11 2603.89,1808.11 2612.57,1799.43 2621.13,1799.43 2633.56,1787 C22.2@2682,1787 ; C22.2@2682,1792 2682,1806 2689,1813 2802,1813 2832,1843 2844,1843 ; 2844,1843.25 2880.14,1843.25 2890.89,1854 v1(2891,1854)
  L3-SIG w10: v1(2175,1313) 2173.09,1314.91 2173.09,1321.98 2172,1323.07 2172,1358.98 2208.02,1395 2742.54,1395 2746.54,1391 2909,1391 v2(2921,1379)
  L3-SIG w25: J4.1@2680,2950 2825,2950 J5.1@2870,2905
  L6 w10: v1@2175,1312 2173.09,1313.91 2173.09,1321.98 2172,1323.07 2172,1407.95 2177.86,1413.81 C23.2@2200,1413.81 ; v1@2365,1948.29 2367,1950.29 v1(2367,1953) 2440,1880 2690,1880 2701,1891 2803.77,1891 2829.77,1865 2880,1865 v1(2891,1854) 2891,1851.29 2921,1821.29 v2(2921,1379)
  L6 w25: J5.1@2870,2905 2884,2891 2884,1861 v1(2891,1854)
VIN_RAW: C4.2 C6.2 C73.2 C93.2 C95.2 C122.2 C123.1 C129.2 C130.2 D4.1 D6.1 D9.1 L5.1 R3.1 R9.1 R60.2 S3.2 U1.1 U1.6 U2.1 U2.6 U12.1 U19.1 U20.1 U22.5 U23.19 | length 2919.6
  L1 w10: v4(375,485) 375.14,484.86 411,484.86 418.2,484.86 439.86,484.86 ; C129.2@410,526.28 410,482.72 C130.2@411,481.72 ; 440,483.69 U23.19@499.86,483.69 ; v1(1055,1345) U2.6@1055,1447.6 ; R9.1@1202.8,1459.8 1209.17,1459.8 R9.1@1215,1465.63 ; R9.1@1216.97,1465.63 1222.8,1459.8 R9.1@1222.8,1457.83 ; U12.1@1355.25,1872.6 1357.85,1870 R60.2@1470,1870 ; U1.6@1410,1312.6 1410,1262.28 1415,1257.28 C4.2@1415,1255 ; C4.2@1417.28,1255 1417.28,1222.72 v1(1418,1222) ; v1(1470,1820) R60.2@1470,1870.31 ; v1(1560,855) v1@1561.73,856.73 ; R3.1@1560.49,1324.49 1569.49,1324.49 1570,1325 R3.1@1570,1330.32 ; v1@1570,1267.71 1575,1262.71 v1(1575,1260) ; D4.1@2746.73,2393.27 2777.73,2393.27 v1(2785,2386) ; D6.1@3231.73,2393.27 3231.73,2368.27 v1(3245,2355) ; U20.1@3722.4,690.25 C95.2@3722.4,737.4 ; C95.2@3722.72,740 v1(3765,740) ; U19.1@3980.25,447.6 C93.2@4035,447.6 ; v1(4030,400) 4030,402.71 4035,407.71 C93.2@4035,447.28
  L1 w20: U2.1@1165,1447.6 1190.6,1447.6 R9.1@1202.8,1459.8 ; R9.1@1222.8,1457.83 1235,1445.63 v1(1235,1410) ; U1.1@1520,1312.6 1548.6,1312.6 R3.1@1560.49,1324.49 ; v1@1561.73,856.73 D9.1@1561.73,883.27 ; v1@1570,1267.71 R3.1@1570,1325
  L3-SIG w10: v4(375,485) 375,580.54 443.77,649.31 443.77,864.77 511,932 511,1031 782,1302 v4(1027,1302)
  L4-SIG w20: v1(1560,855) 1560,1245 v1(1575,1260)
  L6 w10: 890,1395 892.44,1395 955,1395 1005,1345 v1(1055,1345) v1@1060,1345
  other v1: 3310.32,1045.67 3310.32,1095.67 3310.32,1150.67 3325.32,1200.67 3225.32,1205.67 3265.32,1205.67 3365.32,1205.67 3225.32,1240.67 3265.32,1240.67 3305.32,1240.67 3340.32,1240.67 3380.32,1240.67 3225.32,1285.67
VREF_P: C34.2 TP20.1 U3.N18 | length 214.9
  L1 w8: v1(2650,1725) C34.2@2692.28,1725
  L6 w8: v3(2562.48,1630.95) 2563.25,1631.71 2563.25,1638.25 v1(2650,1725) TP20.1@2692.28,1725
VREF_P_J: C128.2 TP52.1 U21.N18 | length 605.1
  L1 w8: C128.2@1593,604.72 1595.28,607 v4(1638,607)
  L3-SIG w8: v3(1302.16,596.26) 1301.4,595.49 1288.51,595.49 1283.82,590.81 1283.82,537.17 1303.47,517.52 1323.7,517.52 1345.18,539 1545,539 1613,607 v4(1638,607)
  L6 w8: TP52.1@1275,665 1275,614.06 1292.75,596.3 1302.12,596.3 v3(1302.16,596.26)
VREG_AON: C126.2 R99.2 TP21.1 U3.U17 | length 462
  L1 w8: v3(2519,1576) U3.U17@2542.8,1552.2
  L6 w8: R99.2@2323.31,1596 2323.31,1502.69 2335,1491 2346,1491 2388,1533 2488,1533 2518.23,1563.23 2518.23,1575.23 v3(2519,1576) 2475,1620 TP21.1@2475,1650
VREG_AON_J: C127.2 R102.2 TP51.1 U21.U17 | length 476.7
  L6 w8: R102.2@1263.69,487 1263.69,488.97 1281.71,507 1281.71,516.75 v3(1282.48,517.52) 1313.48,517.52 1336,495 1416,495 1457,454 TP51.1@1457,425 ; TP51.1@1454,420 1459.95,420 1471.95,432 1482,432 1489,439 1489,456 1509,476 1584,476 1592.28,467.72 C127.2@1626,467.72
VREG_AUX_1V8: C33.2 TP16.1 U3.V18 | length 341.8
  L6 w8: v3(2562.48,1532.52) 2552.52,1532.52 2540,1520 2540,1464.72 C33.2@2559,1445.72 2562.48,1445.72 2581.28,1445.72 2601,1426 2601,1293 TP16.1@2566.5,1258.5
VREG_AUX_1V8_J: C141.2 TP47.1 U21.V18 | length 318.1
  L1 w10: v2(1352.58,319.58) 1354.15,321.15 1402.43,321.15 C141.2@1404,322.72
  L4-SIG w8: v3(1302.16,497.84) 1302.16,369.99 1352.15,320 v2@1354,320
  L6 w8: v3(1302.16,497.84) 1325,475 1345,475 ; TP47.1@1355.32,465 TP47.1@1364.32,456
VREG_LP_1V8: C36.2 TP19.1 U3.W19 | length 316.9
  L1 w8: U3.W19@2582.16,1512.84 2582.16,1483.86 2625.5,1440.52 2625.5,1379.5 v1(2675,1330)
  L6 w8: TP19.1@2635,1340 2635,1297.72 C36.2@2640,1292.72 ; TP19.1@2635,1345 2635.69,1345 2650.69,1330 v1(2675,1330)
VREG_LP_1V8_J: C115.2 TP50.1 U21.W19 | length 238.3
  L1 w8: U21.W19@1321.85,478.15 1321.85,410.87 C115.2@1325,407.72 1373.28,407.72 v1(1424,357)
  L6 w8: TP50.1@1387,380 1409.44,357.56 1423.44,357.56 v1(1424,357)
VSW: L3.1 U3.T19 | length 125.6
  L1 w10: U3.T19@2582.16,1571.89 2587.28,1577 2602,1577
  L1 w20: 2603,1579 2642,1579 2643.02,1580.01 2702.1,1580.01 L3.1@2705,1582.91
VSW_J: L4.1 U21.T19 | length 138.4
  L1 w15: U21.T19@1321.85,537.2 1364.92,537.2
  L1 w25: 1364.92,537.2 1459.29,537.2 L4.1@1460,537.91
W_AUX_RXD: J7.2 U7.AA9 | length 2242.5
  L1 w5: U7.AA9@1822.6,2381.18 1823.56,2382.15 1823.56,2397.56 1830,2404 1865,2404 1872,2411 1872,2441 1846,2467 1846,2621 v2(1861,2636)
  L3-SIG w5: v2(1861,2636) 1861,2662 1843,2680 1843,2752 1872,2781 2366,2781 2415,2732 3097,2732 3282,2917 3447,2917 J7.2@3513,2983
W_AUX_TXD: J6.2 J7.1 U7.Y10 | length 2404
  L1 w5: v2(1821,2639) 1821,2502.93 1818.07,2500 1804,2500 1799,2495 1799,2461 1808,2452 1840,2452 1846.22,2445.78 U7.Y10@1846.22,2428.43 ; J7.1@3414,2998 3414,2939 3427,2926 3539,2926 J6.2@3615,2850
  L3-SIG w5: v2(1821,2639) 1821,2761 1858,2798 2381,2798 2430,2749 3067,2749 3297,2979 J7.1@3409,2979
W_CS: TP67.1 U7.Y6 U8.13 | length 412.9
  L1 w5: U8.13@1653.41,2270 v4(1616,2270) 1603,2283 1603,2424 1609,2430 1620,2430 1642,2452 1728.16,2452 U7.Y6@1751.73,2428.43
  L6 w5: TP67.1@1616,2224 v4(1616,2270)
W_CTS: U6.11 U7.Y18 | length 202.6
  L1 w5: U6.11@1995,2266.18 1995,2352 1989,2358 1989,2395 1999,2405 2031,2405 2035,2409 2035,2428.23 U7.Y18@2035.2,2428.43
W_IRQ: TP70.1 U7.D13 U9.11 | length 545.2
  L1 w3: U7.D13@1917.09,2806.38 1919.71,2809 1985,2809 v4(1996,2820)
  L1 w5: U7.D13@1917.09,2806.38 1966.47,2757 2005,2757 2013,2765 2013,2773 2023,2783 2051,2783 2059,2775 2059,2766 2064,2761 2065,2761 2066,2760 2129,2760 2175,2714 U9.11@2219,2714
  L6 w3: TP70.1@1921,2827 1940,2808 1986,2808 1996,2818 v4(1996,2820)
W_MISO: TP66.1 U7.Y8 U8.12 | length 523.2
  L1 w5: U8.12@1675.32,2266.18 1675.32,2287.68 1672,2291 v4(1628,2291) 1624,2295 1624,2302 1627,2305 1651,2305 1654,2308 1654,2397 1661,2404 1791,2404 1798.98,2411.98 U7.Y8@1798.98,2428.43
  L6 w5: TP66.1@1534,2283 1534,2318 1538,2322 1607,2322 1607.93,2322.93 1628,2302.86 v4(1628,2291)
W_MOSI: TP68.1 U7.AA5 U8.11 | length 404
  L1 w5: v4(1693,2300) 1695,2298 U8.11@1695,2266.18 ; v4(1719,2349) 1728.11,2358.11 U7.AA5@1728.11,2381.18
  L3-SIG w5: v4(1693,2300) 1693,2285 1687,2279 1643,2279 1639,2275 1639,2263 1642,2260 1735,2260 1739,2264 1739,2311 1719,2331 v4(1719,2349)
  L6 w5: TP68.1@1650,2322 1654.78,2317.22 1675.78,2317.22 v4(1693,2300)
W_RESET_N: U7.N16 U9.10 | length 373.9
  L1 w8: U7.N16@1987.95,2593.78 2048.22,2593.78 2060,2582 2060,2575 2065,2570 2118,2570 2181,2633 v4(2181,2635) ; v4(2182,2736) 2182.66,2735.34 2218.16,2735.34 U9.10@2218.82,2734.68
  L3-SIG w8: v4(2181,2635) 2181,2735 v4(2182,2736)
W_RTS: U6.10 U7.AA17 | length 116.3
  L1 w5: U7.AA17@2011.57,2381.18 2014.68,2378.07 U6.10@2014.68,2266.18
W_RXD: U6.13 U7.Y16 | length 209.7
  L1 w5: U6.13@1955.63,2266.18 1955.63,2340.37 1940,2356 1940,2399 1945,2404 1981,2404 1987,2410 1987,2427.47 U7.Y16@1987.95,2428.43
W_SCK: TP69.1 U7.AA7 U8.10 | length 407.3
  L1 w5: U8.10@1714.68,2266.18 1714.68,2293.68 1724,2303 1756,2303 1775.35,2322.35 v4(1845,2322.35) 1881.35,2322.35 1886,2327 1886,2337 1881,2342 1781,2342 1776,2347 ; 1775.35,2347 U7.AA7@1775.35,2381.18
  L6 w5: v4(1845,2322.35) TP69.1@1881.35,2322.35
W_SCL: R46.1 U7.V11 U10.12 | length 561.4
  L1 w5: U7.V11@1869,2478 1873,2482 1873,2496 1876,2499 1936,2499 1961,2474 2004,2474 2012,2482 2012,2492 2017,2497 2055,2497 2059,2493 2059,2482 2067,2474 2121,2474 2169,2426 2213,2426 2257.63,2381.37 2257.63,2367.05 R46.1@2260.68,2364 ; R46.1@2261.68,2365.32 U10.12@2318.82,2365.32
W_SDA: R47.1 U7.V13 U10.13 | length 594.8
  L1 w5: U7.V13@1917.09,2475.67 1922.22,2470.53 1933.47,2470.53 1953,2451 2049,2451 2061,2439 2061,2364 2149,2276 R47.1@2279,2276 ; R47.1@2281,2272 2310,2272 2318.82,2280.82 U10.13@2318.82,2345.63
W_SWD_CLK: J7.4 U7.J4 | length 2329.7
  L1 w5: U7.J4@1704.49,2688.27 1725.73,2688.27 v2(1743,2671)
  L3-SIG w5: v2(1743,2671) 1743,2779 1828,2864 2381,2864 2455,2790 3042,2790 3297,3045 3642,3045 3706,2981 J7.4@3721,2981
W_SWD_DATA: J7.3 U7.L4 | length 2251.5
  L1 w5: U7.L4@1704.49,2641.02 1725.98,2641.02 v2(1743,2624)
  L3-SIG w5: v2(1743,2624) 1767,2648 1767,2777 1837,2847 2072,2847 2077,2852 2360,2852 2442,2770 3048,2770 3306,3028 3573,3028 J7.3@3619,2982
W_TXD: U6.12 U7.AA15 | length 119.6
  L1 w5: U7.AA15@1964.33,2381.18 1964.33,2351.67 1975.32,2340.68 U6.12@1975.32,2266.18
W_WAKEUP: U7.L16 U9.13 | length 245.1
  L1 w5: U7.L16@1987.95,2641.02 2050.02,2641.02 2059,2650 2059,2656 2066,2663 2154,2663 2167,2676 U9.13@2215,2676
pads on no net: D3.3 D3.4 H1.1 H2.1 H3.1 H4.1 J2.4 J7.5 J9. J10.10 J10.11 J10.26 J10.27 J12.10 J12.11 J12.26 J12.27 J14.3 J14.15 J14.16 J14.17 J14.18 J14.19 J14.20 J14.21 J17.9 J17.11 J17.13 J18.1 J18.3 J18.5 J18.8 J19.2 J20.2 SW2. SW3.1 U3.C1 U4.A2 U4.B5 U5.A2 U5.B5 U6.6 U6.9 U7.A5 U7.A11 U7.A15 U7.AA11 U7.AA13 U7.B2 U7.B8 U7.B18 U7.C1 U7.D2 U7.D7 U7.D9 U7.D11 U7.E1 U7.E19 U7.F2 U7.G1 U7.G4 U7.G16 U7.H2 U7.H18 U7.J1 U7.J16 U7.K2 U7.L1 U7.L19 U7.M2 U7.N1 U7.N4 U7.P2 U7.P18 U7.R1 U7.R4 U7.R16 U7.R19 U7.T2 U7.T18 U7.U19 U7.V7 U7.V9 U7.V18 U7.Y12 U7.Y14 U8.6 U8.9 U9.3 U9.6 U9.9 U9.12 U10.4 U10.5 U10.6 U10.9 U10.10 U10.11 U11.24 U11.25 U11.26 U11.27 U13.0 U13.4 U13.5 U15.0 U15.4 U15.5 U17.0 U17.4 U17.5 U18.0 U18.4 U18.5 U21.A6 U21.A7 U21.A8 U21.A9 U21.A10 U21.A11 U21.A12 U21.A15 U21.A16 U21.A17 U21.B3 U21.B4 U21.B6 U21.B7 U21.B8 U21.B9 U21.B11 U21.B12 U21.B13 U21.B14 U21.B15 U21.B18 U21.B19 U21.C1 U21.C2 U21.C3 U21.C19 U21.D1 U21.D2 U21.E2 U21.E5 U21.E6 U21.E7 U21.E9 U21.E10 U21.E11 U21.E12 U21.E13 U21.E14 U21.E15 U21.E18 U21.F1 U21.F2 U21.F5 U21.F15 U21.F18 U21.G1 U21.G2 U21.G15 U21.G18 U21.G19 U21.H1 U21.H2 U21.H15 U21.H18 U21.H19 U21.J1 U21.J2 U21.J9 U21.J15 U21.J18 U21.J19 U21.K1 U21.K2 U21.K8 U21.K12 U21.K15 U21.K18 U21.K19 U21.L1 U21.L8 U21.L9 U21.L11 U21.L12 U21.L15 U21.L18 U21.L19 U21.M1 U21.M2 U21.M19 U21.N1 U21.N2 U21.N5 U21.N15 U21.P1 U21.P2 U21.P5 U21.P15 U21.R1 U21.R2 U21.R5 U21.R6 U21.R7 U21.R8 U21.R11 U21.R12 U21.R13 U21.R15 U21.R19 U21.T2 U21.U1 U21.U2 U21.U3 U21.V1 U21.V3 U21.V4 U21.V5 U21.V9 U21.V10 U21.V11 U21.V13 U21.V14 U21.V15 U21.V16 U21.V17 U21.W4 U21.W5 U21.W9 U21.W10 U21.W11 U21.W14 U21.W15 U21.W16 U23.3 U23.7 U23.8 U23.9 U23.10 U23.13 U23.21 U23.22 U23.25 U23.26 U23.27 U23.31 U23.32
copper on no net: | length 47.3
  L1 w10: 2787.69,1911 v1@2835,1911
  other v1: 2835,1910

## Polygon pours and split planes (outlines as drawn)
GND on L6 "gnd" (solid, remove dead copper, pour order 4): 0,0 0,3100 1300,3100 1300,2900 2400,2900 2400,3100 5150,3100 5150,2630 4885,2365 4885,1300 5150,1035 5150,5
VDD_CORE_0V8 on L6 "gnd" (solid, remove dead copper, pour order 8): 2030,2050 2910,2050 2910,1250 2030,1250
GND on L3-SIG "gnd" (solid, remove dead copper, pour order 1): 0,0 0,3100 1300,3100 1300,2900 2400,2900 2400,3100 5150,3100 5150,2630 4885,2365 4885,1300 5150,1035 5150,5
VDD_CORE_0V8 on L3-SIG "gnd" (solid, remove dead copper, pour order 7): 2900,1250 2030,1250 2030,2050 2910,2050
GND on L4-SIG "gnd" (solid, remove dead copper, pour order 2): 0,0 0,1800 0,3100 1300,3100 1300,2900 2400,2900 2400,3100 5150,3100 5150,2630 4885,2365 4885,1300 5150,1035 5150,5
VDD_CORE_0V8 on L4-SIG "gnd" (solid, remove dead copper, pour order 6): 2040,1950 2900,1950 2900,1250 2040,1250
VDD_CORE_0V8_J on L4-SIG "gnd" (solid, remove dead copper, pour order 5): 1600,375 840,375 840,845 1390,845 1421.65,813.35 1421.65,736.81 1423.19,736.81 1600,560
GND on L1 "gnd rf" (solid, remove dead copper, pour order 0): 0,0 0,3100 1300,3100 1300,2900 2400,2900 2400,3100 5150,3100 5150,2630 4885,2365 4885,1300 5150,1035 5150,5
no net on L5 (PWR) (split plane): 4469.91,2905.09 4380.09,2905.09 4380.09,2999.91 4469.91,2999.91
VIN_RAW on L5 (PWR) (split plane): 3279.91,2300.09 2940,2300.09 2937.39,2299.74 2934.96,2298.74 2932.87,2297.13 2931.27,2295.04 2930.26,2292.61 2929.91,2290 2929.91,1380 2930.26,1377.39 2931.27,1374.96 2932.87,1372.87 2934.96,1371.26 2937.39,1370.26 2940,1369.91 3499.91,1369.91 3499.91,820 3500.26,817.39 3501.27,814.96 3502.87,812.87 3504.96,811.27 3507.39,810.26 3510,809.91 4044.91,809.91 4044.91,370.09 3290.09,370.09 3290.09,1180 3289.74,1182.61 3288.73,1185.04 3287.13,1187.13 3285.04,1188.74 3282.61,1189.74 3280,1190.09 1240.09,1190.09 1240.09,1260 1239.74,1262.61 1238.74,1265.04 1237.13,1267.13 1235.04,1268.74 1232.61,1269.74 1230,1270.09 990.09,1270.09 990.09,1340 990.09,1899.91 1519.91,1899.91 1519.91,1760.09 1494.53,1760.09 1491.92,1759.74 1489.48,1758.74 1487.4,1757.13 1485.79,1755.04 1484.78,1752.61 1484.44,1750 1484.44,1397.47 1484.78,1394.86 1485.79,1392.43 1487.4,1390.34 1504.87,1372.87 1506.96,1371.26 1509.39,1370.26 1512,1369.91 2730,1369.91 2730.05,1369.92 2730.1,1369.91 2731.35,1370.09 2732.61,1370.26 2732.66,1370.28 2732.71,1370.28 2733.87,1370.78 2735.04,1371.26 2735.08,1371.3 2735.13,1371.32 2736.13,1372.1 2737.13,1372.87 2737.16,1372.91 2737.2,1372.94 2737.96,1373.95 2738.73,1374.96 2738.75,1375 2738.79,1375.05 2739.26,1376.22 2739.74,1377.39 2739.75,1377.44 2739.77,1377.49 2739.92,1378.74 2740.09,1380 2740.08,1380.05 2740.09,1380.1 2730.09,2360.05 2730.09,2419.91 3279.91,2419.91
no net on L5 (PWR) (split plane): 4469.91,100.1 4380.09,100.1 4380.09,194.93 4469.91,194.93
no net on L5 (PWR) (split plane): 446.62,2904.09 356.79,2904.09 356.79,2998.92 446.62,2998.92
no net on L5 (PWR) (split plane): 446.33,99.66 356.5,99.66 356.5,194.49 446.33,194.49
V_1V8_R on L5 (PWR) (split plane): 5129.9,2638.32 4870.79,2379.21 4868.29,2376.17 4866.43,2372.69 4865.29,2368.92 4864.9,2365 4864.9,1300 4865.29,1296.08 4866.43,1292.31 4868.29,1288.83 4870.79,1285.79 5129.9,1026.68 5129.9,25.08 20.1,20.12 20.1,3079.9 1324.9,3079.9 1324.9,2930 1325.29,2928.05 1326.4,2926.4 1328.05,2925.29 1330,2924.9 2355,2924.9 2356.95,2925.29 2358.6,2926.4 2359.71,2928.05 2360.1,2930 2360.1,3079.9 5129.9,3079.9
no net on L2 (GND) (split plane): 4469.91,2905.09 4380.09,2905.09 4380.09,2999.91 4469.91,2999.91
no net on L2 (GND) (split plane): 446.62,2904.09 356.79,2904.09 356.79,2998.92 446.62,2998.92
no net on L2 (GND) (split plane): 4469.91,100.1 4380.09,100.1 4380.09,194.93 4469.91,194.93
AG on L2 (GND) (split plane): 679.91,1895 680.24,1892.5 679.91,1890 680.26,1887.39 681.26,1884.96 682.87,1882.87 684.96,1881.26 687.39,1880.26 690,1879.91 1199.91,1879.91 1199.91,1750.09 20.1,1750.09 20.1,2609.91 679.91,2609.91
no net on L2 (GND) (split plane): 446.33,99.66 356.5,99.66 356.5,194.49 446.33,194.49
GND on L2 (GND) (split plane): 5129.9,2638.32 4870.79,2379.21 4868.29,2376.17 4866.43,2372.69 4865.29,2368.92 4864.9,2365 4864.9,1300 4865.29,1296.08 4866.43,1292.31 4868.29,1288.83 4870.79,1285.79 5129.9,1026.68 5129.9,25.08 20.1,20.12 20.1,1729.91 1210,1729.91 1212.61,1730.26 1215.04,1731.26 1217.13,1732.87 1218.74,1734.96 1219.74,1737.39 1220.09,1740 1220.09,1890 1219.74,1892.61 1218.74,1895.04 1217.13,1897.13 1215.04,1898.74 1212.61,1899.74 1210,1900.09 700.09,1900.09 700.09,2620 699.74,2622.61 698.74,2625.04 697.13,2627.13 695.04,2628.74 692.61,2629.74 690,2630.09 20.1,2630.09 20.1,3079.9 1324.9,3079.9 1324.9,2930 1325.29,2928.05 1326.4,2926.4 1328.05,2925.29 1330,2924.9 2355,2924.9 2356.95,2925.29 2358.6,2926.4 2359.71,2928.05 2360.1,2930 2360.1,3079.9 5129.9,3079.9

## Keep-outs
L1:
  region: 4280,2485 4280,1990 4885,1990 4885,2485
Keep-Out Layer:
  circle w6: c450,2360 r43.19
  circle w6: c174.41,2360 r42.35
  circle w6: c3035,900 r24.19
  circle w6: c3035,1049.61 r30.19
  lines w10: 0,0 5150,5 5150,1035 4885,1300 4885,2365 5150,2630 5150,3100 0,3100 0,0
